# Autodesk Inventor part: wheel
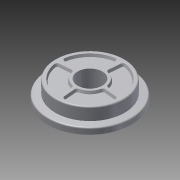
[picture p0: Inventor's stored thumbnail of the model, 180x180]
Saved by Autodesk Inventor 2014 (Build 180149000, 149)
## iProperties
Created: 2009-11
Part Number: wheel
Document SubType Name: Modeling
Designer: pokornp
Density: 1 g/cm^3
Material: Generic
Appearance: Default
Author: pokornp
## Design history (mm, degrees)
sketch "Sketch2"
  geometry: L1 (50, 0)-(50, 80); L2 (50, 80)-(140, 80); L3 (140, 80)-(140, 30); L4 (170, 0)-(50, 0); L5 (0, -16)-(0, 96) reference; L6 (140, 30)-(170, 27.375); L7 (170, 27.375)-(170, 0); 1 further point
  constraints: 12 end point, 3 parallel, 1 horizontal alignment, 1 perpendicular, 1 vertical
  dimensions: "d2" = 80 distance of L1.start L1.end; "d3" = 50 distance from line of point (0, 0) L1; "d4" = 170 distance of point (0, 0) L4.start; "d8" = 5 deg angle of L4 L6; "d9" = 50 distance of L2.end L3.end; "d10" = 90 distance of L1.end L2.end
revolve "Revolution1" sketch "Sketch2" stored, may be unused: angle "d7" = 90 deg
fillet "Fillet1" dims "d11" = 5
sketch "Sketch3"
  geometry: L1 (-69.018, -6.038)-(-114.128, -9.985); L2 (-238, 0)-(238, 0) reference; L3 (0, -238)-(0, 238) reference; L4 (-6.038, -69.018)-(-9.985, -114.128); C1 r 135 at (0, 0) reference; A1 r 125 centre (0, 0) between (-123.105, -21.681) and (-21.681, -123.105); A2 r 60 centre (0, 0) between (-58.412, -13.715) and (-13.715, -58.412); A3 r 10 centre (-19.947, -113.257) between (-21.681, -123.105) and (-9.985, -114.128); A4 r 10 centre (-113.257, -19.947) between (-114.128, -9.985) and (-123.105, -21.681); A5 r 10 centre (-68.147, -16) between (-58.412, -13.715) and (-69.018, -6.038); A6 r 10 centre (-16, -68.147) between (-6.038, -69.018) and (-13.715, -58.412); 4 further points
  constraints: 16 point on circle, 8 tangent, 6 centre point, 4 end point, 4 point on line, 3 equal radius, 2 coincident
  dimensions: "d12" = 120 diameter of A2; "d13" = 250 diameter of A1; "d14" = 5 deg angle of L1 L2; "d16" = 10 radius of A3
extrude "Extrusion1" cut sketch "Sketch3" distance "d17" = 10; taper "d18" = -20 deg
pattern_circular "Circular Pattern1" dims angle "d20" = 360 deg
workplane "Work Plane1"
body "Solid1"
other parameters: "d15" = 5 deg
